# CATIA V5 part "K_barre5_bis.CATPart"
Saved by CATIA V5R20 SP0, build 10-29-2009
Part number: barre_5_bis
Bounding box of the stored display mesh (mm): x -50.981 to -11.018, y -11 to -10, z -10.505 to -4.008
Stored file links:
  G:\Khaled_CFAO_2011\ST2M\ST2M_GR2\gcausse\Khaled\CAD_ThinkMotion\K_barre5_bis.CATPart
  C:\Documents and Settings\gcausse\Bureau\video thinkmotio\assemblage_gcausse\pupitre_think.CATProduct
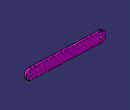
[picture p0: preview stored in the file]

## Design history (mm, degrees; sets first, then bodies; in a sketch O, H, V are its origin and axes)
Set1
  Sketch1 on Plane1, origin (0, -11, 0), H (-1, 0, 0), V (0, 0, 1)
    line L1 (48.5907, -5.5101) -> (13.6229, -4.0082)
    arc A1 centre (13.5157, -6.5059) radius 2.5 from (13.6229, -4.0082) to (13.4084, -9.0036) ccw
    point P3 (13.5157, -6.5059)
    line L2 (13.4084, -9.0036) -> (48.3762, -10.5055)
    arc A2 centre (48.4834, -8.0078) radius 2.5 from (48.3762, -10.5055) to (48.5907, -5.5101) ccw
    point P6 (48.4834, -8.0078)
    reference projected point E1 (13.5157, -6.5059) from Point1
    reference projected point E2 (48.4834, -8.0078) from Point2
    reference projected line E3 (48.4834, -8.0078) -> (13.5157, -6.5059) from Line1
    reference projected line E4 (48.4834, -8.0078) -> (13.5157, -6.5059) from Line1
    distance L1 L2 = 5
    tangency: A1 L1, L2 A1, A2 L1, A2 L2
    coincidence: P3 E1, P6 E2
    parallelism: L1 E3, E4 L2
Set2
  Plane1: linked copy from another document
  Point1: linked copy from another document
  Point2: linked copy from another document
  Line1: linked copy from another document
Body1 (main body)
  Pad1: profile Sketch1, direction (0, 1, 0), length 1
  Sketch2 on start face of Pad1, origin (-37.4976, -11, -5.7724), H (1, 0, 0), V (0, 0, 1)
    point P1 (-10.9858, -2.2354)
    reference projected point E1 (-10.9858, -2.2354) from Point2
    coincidence: P1 E1
  Hole1: placed by Sketch2, at (-48.4834, -11, -8.0078) direction (0, 1, 0), diameter 1, depth 1
  Sketch3 on start face of Pad1, origin (-17.7493, -11, -5.7952), H (1, 0, 0), V (0, 0, 1)
    point P1 (4.2336, -0.7107)
    reference projected point E1 (4.2336, -0.7107) from Point1
    coincidence: P1 E1
  Hole2: placed by Sketch3, at (-13.5157, -11, -6.5059) direction (0, 1, 0), diameter 1, depth 1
